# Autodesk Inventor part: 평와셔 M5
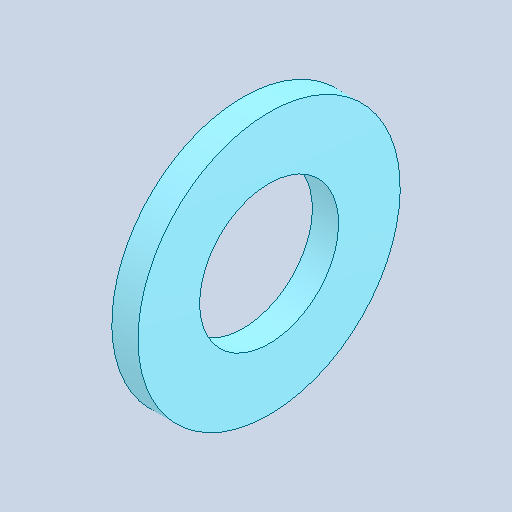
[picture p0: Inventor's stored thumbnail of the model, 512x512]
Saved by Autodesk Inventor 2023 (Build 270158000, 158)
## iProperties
Created: 2024-09
Part Number: 평와셔 M5
Material: 강철, 연강
Description: 평면 와셔
Document SubType Name: Modeling
Designer: home
Density: 7.85 g/cm^3
Appearance: 기본값
Author: jhkim
Sending System: Autodesk Inventor 2025
Preprocessor: ST-DEVELOPER v20
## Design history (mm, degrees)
feature "Solid1"
node "솔리드1"
